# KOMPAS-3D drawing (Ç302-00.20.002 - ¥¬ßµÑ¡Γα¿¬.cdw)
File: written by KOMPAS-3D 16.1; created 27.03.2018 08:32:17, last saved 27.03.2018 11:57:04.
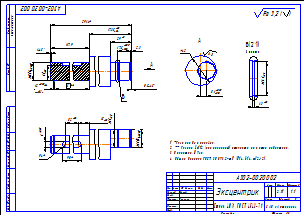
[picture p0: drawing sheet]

Sheet 1: A3, landscape

Title block, sheet 1: name: Эксцентрик; designation: А302-00.20.002; material: Сталь 40Х  ГОСТ 4543-71; mass: 2,11; scale: 1:1; sheets: 1; organisation: ЗАО «Астерион»; sheet format: A3; stored path: Z:\Мембранные насосы\Мембранный электропривод\А302-00.00.000 - ASTRA-302 (МЭ200)\Чертежи\А302-00.20.002 - Эксцентрик.cdw; drawn by: Милов; technical control: Лучихин

Views: Вид 1, Вид:3, Проекционный вид 3, Местный разрез 1, Выносной элемент 4, Вид по стрелке 5, Выносной элемент Б, Выносной элемент
Referenced files in Z:\Мембранные насосы\Мембранный электропривод\А302-00.00.000 - ASTRA-302 (МЭ200)\3Д\: А302-00.20.002 - Эксцентрик.m3d
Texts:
  шайба
  *Размеры для справок.
  ** Размер L=112 (номинальный) уточнить по мотор редуктору.
  Покрытие: Ц9хр.
  Общие допуски ГОСТ 30893.2-mK (H14, h14,  t2/2).
  Ra 3,2
  Ra 3,2 ( )
Dimensions and other numbers on the sheet: 8; 4; 82; 15; 90; 25; 29; 117,9; 1; 0,5; 21; 2,3; 17,5; 173,5; 291,4; 1,2; 3 места; 23,8; 1,3; 8,1; 42; 6,3; 1:1; 2,11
